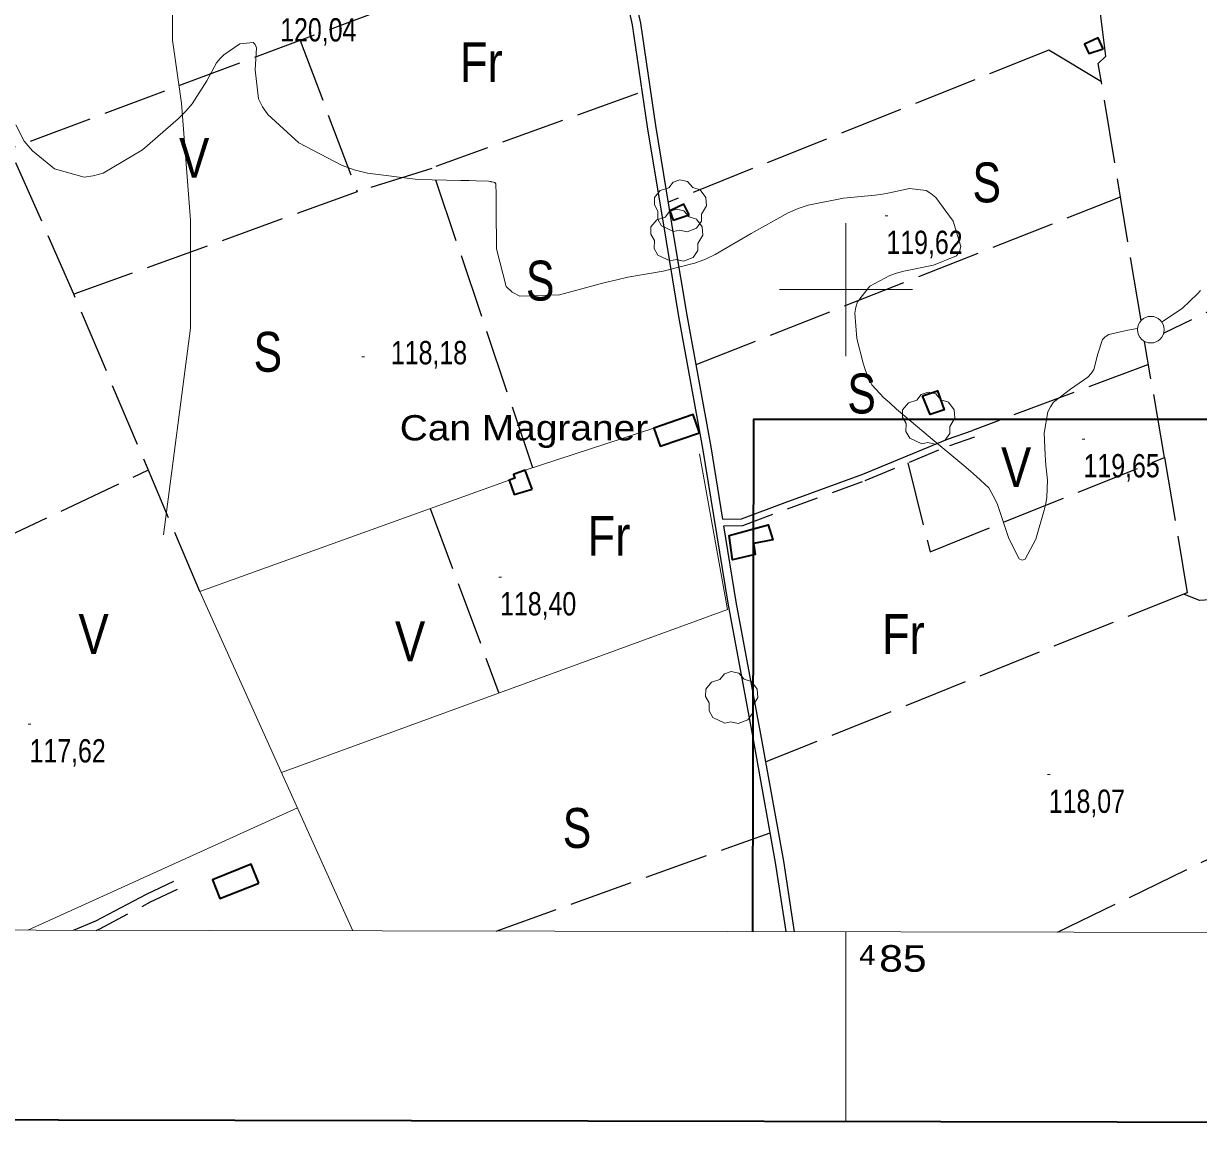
# Model space of a CAD drawing. Extents: x 483855 to 488461, y 4388206 to 4391419.
# Drawn here: x 484690.9 to 485132.5, y 4388682 to 4389100 of the extents above; entities that cross this region are included whole.
import ezdxf
from ezdxf.enums import TextEntityAlignment as Align

# ---------------------------------------------------------------- set-up
doc = ezdxf.new("R2010")
doc.units = 0
doc.header["$LTSCALE"] = 4
for name, pattern in [('DOTTED', [1.5, 0.3, -1.2]), ('LONG_DASHED', [7.5, 6, -1.5]), ('MEDIUM_DASHED', [4.5, 3, -1.5])]:
    doc.linetypes.add(name, pattern=pattern)
for name, color, linetype, lineweight in [('1', 7, 'Continuous', 13), ('2', 7, 'DOTTED', 13), ('22', 7, 'Continuous', 13), ('24', 7, 'Continuous', 13), ('25', 7, 'LONG_DASHED', 25), ('29', 7, 'Continuous', 13), ('38', 7, 'Continuous', 25), ('47', 7, 'Continuous', 35), ('51', 7, 'Continuous', 13), ('63', 7, 'Continuous', 35), ('7', 7, 'Continuous', 13), ('9', 7, 'Continuous', 13)]:
    doc.layers.add(name, color=color, linetype=linetype, lineweight=lineweight)
doc.layers.add('31', color=7, linetype='Continuous')
doc.layers.add('5', color=7, linetype='Continuous')

msp = doc.modelspace()

# ---------------------------------------------------------------- linework, layer by layer
at = {"layer": '1'}
for p, q in [((485000, 4389025), (485000, 4388975)), ((484975, 4389000), (485025, 4389000)), ((485000, 4388758.61), (485000, 4388687.26))]:
    msp.add_line(p, q, dxfattribs=at)
at = {"layer": '1', "lineweight": 35}
msp.add_lwpolyline([(484045.03, 4391144.08), (487760.33, 4391137.02), (487755.66, 4388682.02), (484040.36, 4388689.09)], close=True, dxfattribs=at)
at = {"layer": '1'}
msp.add_lwpolyline([(484115.5, 4391072.6), (487689.7, 4391065.7), (487685.8, 4388753.5), (484110.5, 4388760.3)], close=True, dxfattribs=at)
at = {"layer": '22'}
msp.add_circle((485114.62, 4388984.95), 5, dxfattribs=at)
at = {"layer": '24'}
msp.add_lwpolyline([(484618.34, 4389333.89), (484638.63, 4389310.22), (484655.54, 4389293.31), (484665.68, 4389279.78), (484689.36, 4389259.49), (484713.03, 4389232.44), (484729.94, 4389208.76), (484746.85, 4389171.56), (484746.85, 4389093.78), (484750.23, 4389070.11), (484753.61, 4389026.14), (484753.61, 4388985.56), (484743.47, 4388907.78)], dxfattribs=at)
at = {"layer": '25'}
for p, q in [((484912.53, 4389137.57), (484685.65, 4389052.88)), ((484794.88, 4389093.66), (484816.28, 4389036.74)), ((484921.65, 4389073.78), (484845.79, 4389046.31)), ((484943.69, 4388971.85), (485103.22, 4389034.9)), ((485119.8, 4388936.87), (485112.23, 4388980.53)), ((485113.74, 4388971.87), (485047.6, 4388947.08)), ((484542.23, 4388839.87), (484737.79, 4388932.2)), ((484843.71, 4388917.68), (484869.59, 4388848.34)), ((484868.47, 4388758.86), (484971.56, 4388795.84))]:
    msp.add_line(p, q, dxfattribs=at)
for points in [[(484757.11, 4388886.54), (484709.82, 4388998.24), (484685.65, 4389052.88), (484652.91, 4389123.32), (484607.37, 4389218.91)], [(485110.93, 4388988.41), (485094.88, 4389085.06), (485097.72, 4389087.76), (485093.16, 4389123.91)], [(485096.04, 4389078.12), (485076.27, 4389090.05), (484933.29, 4389032.85)], [(484882.3, 4388933.06), (484844.4, 4389045.49), (484816.27, 4389036.79), (484709.82, 4388998.24)], [(485253.12, 4388863.98), (485220.04, 4388925.41), (485227.31, 4388929.17), (485183.88, 4389014.77), (485119.45, 4388983.6)], [(485023.25, 4388934.86), (485031.64, 4388901.47), (485119.8, 4388936.87), (485119.8, 4388936.87), (485128.29, 4388886.03), (484969.9, 4388822.48)], [(485163.83, 4388891.94), (485157.92, 4388883.67), (485148.99, 4388884.11), (485132.94, 4388883.18), (485127.03, 4388885.53)], [(485079.57, 4388758.46), (485139.1, 4388787.33), (485259.96, 4388849.16)]]:
    msp.add_lwpolyline(points, dxfattribs=at)
at = {"layer": '29'}
for points in [[(484935.21, 4389021.83), (484930.67, 4389023.95), (484929.26, 4389026.49), (484929.36, 4389029.47), (484927.99, 4389031.88), (484928.03, 4389034.63), (484930.19, 4389037.23), (484933.38, 4389038.23), (484935.03, 4389040.42), (484937.6, 4389041.25), (484940.46, 4389040.6), (484942.41, 4389038.33), (484945.22, 4389037.51), (484947.35, 4389034.66), (484947.59, 4389031.53), (484945.71, 4389028.38), (484945.71, 4389025.7), (484943.89, 4389023.09), (484940.27, 4389021.75), (484937.5, 4389022.38)], [(484933.88, 4389010.8), (484929.34, 4389012.92), (484927.93, 4389015.46), (484928.03, 4389018.44), (484926.66, 4389020.85), (484926.7, 4389023.6), (484928.86, 4389026.2), (484932.05, 4389027.2), (484933.7, 4389029.39), (484936.27, 4389030.22), (484939.13, 4389029.57), (484941.08, 4389027.3), (484943.89, 4389026.48), (484946.02, 4389023.63), (484946.26, 4389020.5), (484944.38, 4389017.35), (484944.38, 4389014.67), (484942.56, 4389012.06), (484938.94, 4389010.72), (484936.17, 4389011.35)], [(485028.51, 4388942.01), (485023.97, 4388944.13), (485022.56, 4388946.67), (485022.66, 4388949.65), (485021.29, 4388952.06), (485021.33, 4388954.81), (485023.49, 4388957.41), (485026.68, 4388958.41), (485028.33, 4388960.6), (485030.9, 4388961.43), (485033.76, 4388960.78), (485035.71, 4388958.51), (485038.52, 4388957.69), (485040.65, 4388954.84), (485040.89, 4388951.71), (485039.01, 4388948.56), (485039.01, 4388945.88), (485037.19, 4388943.27), (485033.57, 4388941.93), (485030.8, 4388942.56)], [(484954.49, 4388837.02), (484949.95, 4388839.14), (484948.54, 4388841.68), (484948.64, 4388844.66), (484947.27, 4388847.07), (484947.31, 4388849.82), (484949.47, 4388852.42), (484952.66, 4388853.42), (484954.31, 4388855.61), (484956.88, 4388856.44), (484959.74, 4388855.79), (484961.69, 4388853.52), (484964.5, 4388852.7), (484966.63, 4388849.85), (484966.87, 4388846.72), (484964.99, 4388843.57), (484964.99, 4388840.89), (484963.17, 4388838.28), (484959.55, 4388836.94), (484956.78, 4388837.57)]]:
    msp.add_lwpolyline(points, close=True, dxfattribs=at)
at = {"layer": '38'}
for points in [[(484953.75, 4388913.69), (484949.31, 4388940.94), (484940.3, 4388990.45), (484935.62, 4389018.77), (484928.5, 4389061.64), (484922.87, 4389100.12), (484919.4, 4389115.79), (484916.17, 4389125), (484915.91, 4389129.2), (484916.45, 4389135.55), (484917.18, 4389136.34), (484923.41, 4389139.34), (484938.34, 4389144.79), (484968.72, 4389156.14), (484992.53, 4389163.87), (485016.02, 4389170.76), (485032.98, 4389177.54), (485052.17, 4389185.75), (485053.9, 4389188.19)], [(484977.54, 4388758.65), (484973.59, 4388784.59), (484964.96, 4388832.28), (484955.72, 4388882.15), (484946.25, 4388940.42), (484937.24, 4388989.92), (484932.55, 4389018.27), (484925.43, 4389061.16), (484919.81, 4389099.56), (484916.41, 4389114.93), (484913.09, 4389124.38), (484912.79, 4389129.24), (484913.38, 4389136.13)], [(484953.75, 4388913.69), (484960.8, 4388913.86), (484977.13, 4388920.03), (485006.37, 4388930.58), (485038.15, 4388943.84), (485047.6, 4388947.08)], [(484980.69, 4388758.64), (484976.66, 4388785.1), (484968.02, 4388832.84), (484958.78, 4388882.68), (484954.15, 4388911.15)], [(484709.64, 4388759.16), (484718.09, 4388762.71), (484737.12, 4388772.79), (484747.39, 4388777.61)]]:
    msp.add_lwpolyline(points, dxfattribs=at)
at = {"layer": '38', "linetype": 'MEDIUM_DASHED'}
for points in [[(484954.15, 4388911.15), (484961.3, 4388911.33), (484978.01, 4388917.64), (485007.29, 4388928.2), (485039.06, 4388941.46), (485048.43, 4388944.67)], [(484718.14, 4388759.14), (484719.5, 4388759.73), (484738.59, 4388769.84), (484748.79, 4388774.63)]]:
    msp.add_lwpolyline(points, dxfattribs=at)
at = {"layer": '47'}
for points in [[(485096.74, 4389090.54), (485094.79, 4389094.66), (485089.62, 4389092.21), (485091.25, 4389088.74)], [(484941.04, 4389028.1), (484939.01, 4389032.07), (484933.85, 4389029.6), (484935.09, 4389026.15)], [(485028.77, 4388960.05), (485034.39, 4388962.01), (485036.88, 4388954.86), (485031.71, 4388953.08)], [(484945, 4388946.12), (484942.59, 4388953.02), (484927.81, 4388947.86), (484930.14, 4388941.16)], [(484882.03, 4388925.01), (484879.46, 4388932.13), (484875.02, 4388930.55), (484875.53, 4388929.1), (484873.38, 4388928.34), (484875.27, 4388922.96)], [(484965.32, 4388904.51), (484965.93, 4388900.46), (484957.38, 4388898.42), (484956.17, 4388907.57), (484970.71, 4388911.57), (484972.52, 4388905.95)], [(484779.27, 4388776.83), (484776.41, 4388783.96), (484761.88, 4388778.15), (484764.7, 4388771.08)]]:
    msp.add_lwpolyline(points, close=True, dxfattribs=at)
at = {"layer": '51'}
for p, q in [((484927.81, 4388947.86), (484879.46, 4388932.13)), ((484873.38, 4388928.34), (484757.11, 4388886.54)), ((484814.7, 4388758.96), (484757.11, 4388886.54)), ((484793.84, 4388805.19), (484692.49, 4388759.19))]:
    msp.add_line(p, q, dxfattribs=at)
msp.add_lwpolyline([(484787.85, 4388818.47), (484955.54, 4388879.74), (484945.02, 4388938.24)], dxfattribs=at)
at = {"layer": '63'}
msp.add_lwpolyline([(484965.05, 4388758.67), (484965.36, 4388951.31), (485486.21, 4388951.31), (485486.51, 4388757.68)], dxfattribs=at)
at = {"layer": '7'}
for p, q in [((485014.73, 4389027.77), (485015.73, 4389027.77)), ((484818.06, 4388974.79), (484819.06, 4388974.79)), ((485088.83, 4388943.8), (485089.83, 4388943.8)), ((484869.5, 4388891.9), (484870.5, 4388891.9)), ((484692.63, 4388836.63), (484693.63, 4388836.63)), ((485075.76, 4388817.68), (485076.76, 4388817.68))]:
    msp.add_line(p, q, dxfattribs=at)
at = {"layer": '9'}
for points in [[(485010.98, 4389035.56), (484999.15, 4389034.41), (484985.78, 4389031.77), (484982.03, 4389030.45), (484978.25, 4389028.88), (484964.42, 4389021.08), (484950.83, 4389013.16), (484947.2, 4389011.51), (484943.64, 4389010.1), (484931.26, 4389006.95), (484917.99, 4389004.62), (484913.86, 4389003.72), (484909.54, 4389002.7), (484892.29, 4388998.1), (484877.38, 4388997.5), (484874.54, 4388999), (484872.25, 4389001.22), (484868.59, 4389015.29), (484868.53, 4389030.48), (484868.51, 4389033.41), (484868.48, 4389035.79), (484868.34, 4389039.77), (484868.11, 4389040.09), (484868.02, 4389040.17), (484867.92, 4389040.23), (484867.48, 4389040.41), (484866.88, 4389040.54), (484866.69, 4389040.58), (484866.49, 4389040.61), (484865.64, 4389040.74), (484861, 4389040.91), (484858.4, 4389040.97), (484855.23, 4389041.05), (484839.05, 4389041.37), (484820.1, 4389043.72), (484815.19, 4389045.07), (484810.42, 4389046.73), (484794.41, 4389055.23), (484782.73, 4389065.81), (484780.68, 4389068.77), (484779.16, 4389071.75), (484777.96, 4389082.64), (484778.4, 4389090.83), (484777.9, 4389092.1), (484777.13, 4389092.95), (484772.14, 4389092.45), (484766.14, 4389088.3), (484764.74, 4389086.85), (484763.45, 4389085.27), (484759.75, 4389078.49), (484754.24, 4389069.87), (484751.82, 4389067.14), (484749, 4389064.25), (484735.56, 4389052.6), (484720.78, 4389043.81), (484717.1, 4389042.73), (484713.61, 4389042.25), (484702.54, 4389045.41), (484694.28, 4389052.21), (484692.58, 4389054.01), (484691.12, 4389055.78), (484687.94, 4389061.9)], [(485109.5, 4388985.36), (485106, 4388984.74), (485098.87, 4388983.13), (485097.51, 4388982.26), (485096.42, 4388981.22), (485094.7, 4388975.91), (485093.13, 4388969.92), (485092.15, 4388968.44), (485090.92, 4388967.03), (485084.47, 4388962.6), (485078.06, 4388957.67), (485076.86, 4388955.96), (485075.91, 4388954.09), (485074.52, 4388946.08), (485074.84, 4388937.88), (485074.97, 4388935.89), (485075.11, 4388934.03), (485075.74, 4388928.32), (485075.52, 4388921.95), (485075.12, 4388919.66), (485074.58, 4388917.15), (485071.41, 4388906.21), (485067.35, 4388898.7), (485066.25, 4388898.35), (485065.15, 4388898.75), (485061.25, 4388906.45), (485057.76, 4388917.02), (485056.92, 4388919.24), (485056.13, 4388921.15), (485053.72, 4388925.48), (485049.09, 4388929.8), (485046.89, 4388931.7), (485044.3, 4388933.91), (485031.65, 4388944.45), (485019.02, 4388955.1), (485016.45, 4388957.38), (485014.28, 4388959.37), (485009.77, 4388964.16), (485007.74, 4388968.6), (485007.13, 4388970.37), (485006.51, 4388972.38), (485004.09, 4388981.6), (485003.3, 4388991.16), (485003.69, 4388993.38), (485004.36, 4388995.42), (485008.99, 4389001.25), (485016.55, 4389005.27), (485019.06, 4389006.18), (485021.74, 4389006.99), (485032.95, 4389009.16), (485041.61, 4389012.66), (485042.69, 4389014.32), (485043.2, 4389016.26), (485040.28, 4389025.77), (485033.74, 4389034.6), (485031.95, 4389036.13), (485030.19, 4389037.26), (485023.91, 4389038.02), (485016.35, 4389036.35), (485013.77, 4389035.94), (485010.98, 4389035.56)], [(485133.23, 4388999.71), (485132.14, 4388998.36), (485126.41, 4388992.88), (485118.95, 4388988.01), (485118.66, 4388987.88)]]:
    msp.add_lwpolyline(points, dxfattribs=at)

# ---------------------------------------------------------------- texts
at = {"layer": '2'}
for s, height, width, p in [('4', 7.5, 1.1, (485004.99, 4388746.1)), ('85  ', 10, 1.2, (485012.48, 4388743.59))]:
    msp.add_text(s, height=height, rotation=359.891, dxfattribs=dict(at, width=width)).set_placement(p)
at = {"layer": '31'}
for s, width, p in [('Fr', 0.85, (484862.93, 4389078.02)), ('V', 0.85, (484755.02, 4389042.03)), ('S', 0.8, (485052.93, 4389032.8)), ('S', 0.8, (484885.08, 4388995.89)), ('S', 0.8, (484782.7, 4388969.13)), ('S', 0.8, (485005.9, 4388953.45)), ('V', 0.85, (485063.99, 4388925.76)), ('Fr', 0.85, (484910.89, 4388899.93)), ('V', 0.85, (484717.21, 4388863.02)), ('Fr', 0.85, (485021.57, 4388863.02)), ('V', 0.85, (484836.18, 4388860.25)), ('S', 0.8, (484898.91, 4388790.12))]:
    msp.add_text(s, height=15, dxfattribs=dict(at, width=width)).set_placement(p, align=Align.CENTER)
at = {"layer": '5', "width": 1.15}
msp.add_text('Can Magraner', height=9.5, dxfattribs=at).set_placement((484832.29, 4388943.32))
at = {"layer": '7', "width": 0.8}
for s, p in [('120,04', (484787.36, 4389093.29)), ('119,62', (485015.23, 4389013.4)), ('118,18', (484828.96, 4388971.93)), ('119,65', (485089.33, 4388929.43)), ('118,40', (484870, 4388877.53)), ('117,62', (484693.13, 4388822.26)), ('118,07', (485076.26, 4388803.31))]:
    msp.add_text(s, height=8.75, dxfattribs=at).set_placement(p)

doc.saveas('drawing.dxf')
